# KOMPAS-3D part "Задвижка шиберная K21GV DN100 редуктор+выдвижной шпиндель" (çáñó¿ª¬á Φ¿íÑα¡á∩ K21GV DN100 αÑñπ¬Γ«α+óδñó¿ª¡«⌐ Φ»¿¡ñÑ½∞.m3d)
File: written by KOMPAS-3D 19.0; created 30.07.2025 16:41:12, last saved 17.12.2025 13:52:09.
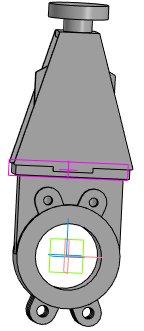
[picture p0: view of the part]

Document properties: Полное имя файла: Задвижка шиберная K21GV DN100 редуктор+выдвижной шпиндель.a3d

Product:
- Part/product: Задвижка шиберная K21GV DN100 редуктор+выдвижной шпиндель
    Масса: 20.5957
  - Body: Тело 1
      Масса: 11.9704

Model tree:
1. Операция без истории:1
2. Эскиз:1  (with: Операция без истории:1)
3. Элемент выдавливания:1
     Расстояние 2 = 300
4. Эскиз:2  (with: Операция без истории:1)
5. Элемент выдавливания:2
     Расстояние 2 = 40
6. Элемент выдавливания:3  (with: Операция без истории:1)
     Расстояние 2 = 40
7. Эскиз:3  (with: Элемент выдавливания:1)
8. Элемент выдавливания:4
     Расстояние 1 = 31
9. Эскиз:4  (with: Операция без истории:1)
10. Элемент вращения:1
     Угол 1 = 360
11. Эскиз:5  (with: Операция без истории:1)
12. Эскиз:6  (with: Операция без истории:1, Элемент вращения:1)
13. Элемент выдавливания:5  (with: Операция без истории:1)
     Расстояние 2 = 3
14. Эскиз:7  (with: Операция без истории:1, Элемент вращения:1)
15. Элемент выдавливания:6  (with: Операция без истории:1)
     Расстояние 1 = -3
